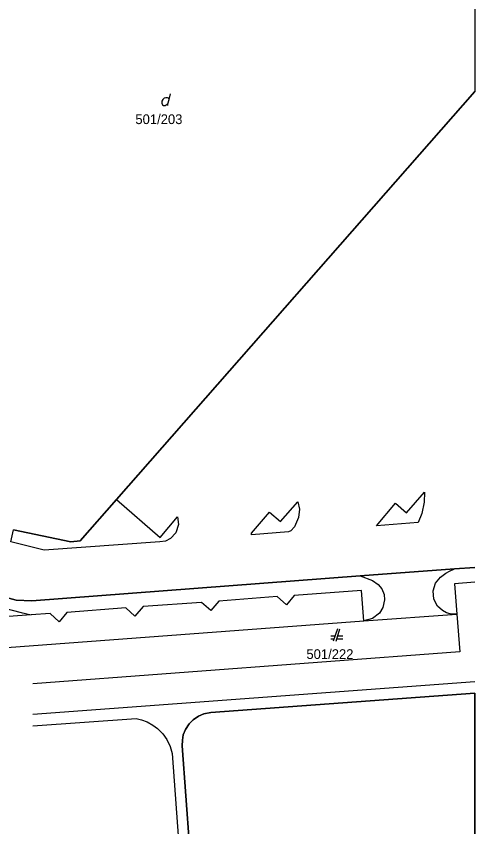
# Model space of a CAD drawing. Extents: x -264309 to -263505, y -1242443 to -1241763.
# Drawn here: x -263664.7 to -263589.3, y -1242279.4 to -1242146.2 of the extents above; entities that cross this region are included whole.
import ezdxf

# ---------------------------------------------------------------- set-up
doc = ezdxf.new("R2010")
doc.units = 0
for name, color, linetype in [('KN_2019_08_16', 7, 'Continuous'), ('KN_2019_08_16_KLADPAR', 7, 'Continuous'), ('KN_2019_08_16_ZAPPAR', 7, 'Continuous')]:
    doc.layers.add(name, color=color, linetype=linetype)

msp = doc.modelspace()

# ---------------------------------------------------------------- linework, layer by layer
at = {"layer": 'KN_2019_08_16'}
for p, q in [((-263689.32, -1242251.71), (-263607.55, -1242245.57)), ((-263607.55, -1242245.57), (-263592.26, -1242244.49)), ((-263592.26, -1242244.49), (-263591.75, -1242250.71)), ((-263591.75, -1242250.71), (-263661.97, -1242255.96))]:
    msp.add_line(p, q, dxfattribs=at)
at = {"layer": 'KN_2019_08_16_KLADPAR'}
for p, q in [((-263589.31, -1242136.09), (-263589.31, -1242158.57)), ((-263589.31, -1242158.57), (-263648.25, -1242225.66)), ((-263639.59, -1242159.89), (-263639.32, -1242158.99)), ((-263648.25, -1242225.66), (-263654.22, -1242232.42)), ((-263655.72, -1242232.61), (-263665.17, -1242230.64)), ((-263654.22, -1242232.42), (-263655.72, -1242232.61)), ((-263608.15, -1242238.19), (-263592.66, -1242237.06)), ((-263592.66, -1242237.06), (-263589.31, -1242236.82)), ((-263662.17, -1242242.32), (-263608.15, -1242238.19)), ((-263667.15, -1242241.55), (-263664.7, -1242242.17)), ((-263664.7, -1242242.17), (-263662.17, -1242242.32)), ((-263611.91, -1242246.93), (-263612.61, -1242248.93)), ((-263612.11, -1242248.93), (-263611.51, -1242246.93)), ((-263612.33, -1242248.13), (-263613.01, -1242248.13)), ((-263611.01, -1242248.13), (-263611.87, -1242248.13)), ((-263613.01, -1242248.53), (-263612.47, -1242248.53)), ((-263611.99, -1242248.53), (-263611.01, -1242248.53)), ((-263589.31, -1242257.5), (-263632.7, -1242260.67)), ((-263632.7, -1242260.67), (-263589.31, -1242257.5)), ((-263589.31, -1242316.35), (-263589.31, -1242257.5)), ((-263589.31, -1242257.5), (-263589.31, -1242316.35)), ((-263634.73, -1242261.26), (-263635.63, -1242261.87)), ((-263635.63, -1242261.87), (-263634.73, -1242261.26)), ((-263633.86, -1242260.9), (-263634.73, -1242261.26)), ((-263634.73, -1242261.26), (-263633.86, -1242260.9)), ((-263632.7, -1242260.67), (-263633.86, -1242260.9)), ((-263633.86, -1242260.9), (-263632.7, -1242260.67)), ((-263636.29, -1242262.54), (-263636.89, -1242263.47)), ((-263636.89, -1242263.47), (-263636.29, -1242262.54)), ((-263635.63, -1242261.87), (-263636.29, -1242262.54)), ((-263636.29, -1242262.54), (-263635.63, -1242261.87)), ((-263637.24, -1242264.33), (-263637.4, -1242265.2)), ((-263637.4, -1242265.2), (-263637.24, -1242264.33)), ((-263636.89, -1242263.47), (-263637.24, -1242264.33)), ((-263637.24, -1242264.33), (-263636.89, -1242263.47)), ((-263637.4, -1242265.2), (-263637.43, -1242266.15)), ((-263637.43, -1242266.15), (-263637.4, -1242265.2)), ((-263637.43, -1242266.15), (-263633.91, -1242314.48)), ((-263633.91, -1242314.48), (-263637.43, -1242266.15))]:
    msp.add_line(p, q, dxfattribs=at)
for points in [[(-263665.17, -1242230.64), (-263655.72, -1242232.61), (-263654.22, -1242232.42), (-263648.25, -1242225.66), (-263589.31, -1242158.57)], [(-263639.77, -1242160.88), (-263639.77, -1242160.61), (-263639.59, -1242159.89), (-263639.68, -1242159.71), (-263639.86, -1242159.62), (-263640.13, -1242159.62), (-263640.4, -1242159.71), (-263640.58, -1242159.89), (-263640.76, -1242160.16), (-263640.76, -1242160.52), (-263640.67, -1242160.79), (-263640.49, -1242160.88), (-263640.22, -1242160.88), (-263640.04, -1242160.79), (-263639.77, -1242160.61)], [(-263589.31, -1242236.82), (-263592.66, -1242237.06), (-263608.15, -1242238.19), (-263662.17, -1242242.32), (-263664.7, -1242242.17), (-263667.15, -1242241.55)]]:
    msp.add_lwpolyline(points, dxfattribs=at)
at = {"layer": 'KN_2019_08_16_ZAPPAR'}
for p, q in [((-263598.6, -1242229.45), (-263605.47, -1242229.95)), ((-263619.95, -1242230.99), (-263626.01, -1242231.45)), ((-263641.11, -1242232.58), (-263660.13, -1242233.99)), ((-263589.31, -1242239.25), (-263592.67, -1242239.5)), ((-263634.24, -1242242.56), (-263643.86, -1242243.26)), ((-263661.97, -1242260.91), (-263589.31, -1242255.57))]:
    msp.add_line(p, q, dxfattribs=at)
for points in [[(-263605.47, -1242229.95), (-263602.36, -1242226.23), (-263600.57, -1242227.85), (-263597.61, -1242224.45), (-263597.66, -1242226.07), (-263598, -1242227.95), (-263598.6, -1242229.45)], [(-263648.25, -1242225.66), (-263641.07, -1242231.91), (-263638.19, -1242228.5), (-263638.05, -1242229.78), (-263638.47, -1242231.1), (-263639.33, -1242232.07), (-263640.17, -1242232.49), (-263641.11, -1242232.58)], [(-263626.01, -1242231.45), (-263626.04, -1242231.19), (-263623.09, -1242227.72), (-263621.25, -1242229.25), (-263618.41, -1242226.02)], [(-263618.41, -1242226.02), (-263618.16, -1242227.26), (-263618.29, -1242228.59), (-263618.98, -1242230.12), (-263619.57, -1242230.81), (-263619.95, -1242230.99)], [(-263660.13, -1242233.99), (-263665.58, -1242232.61), (-263665.17, -1242230.64)], [(-263592.67, -1242239.5), (-263592.26, -1242244.49), (-263592.78, -1242244.51), (-263593.34, -1242244.45), (-263593.95, -1242244.28), (-263594.63, -1242243.87), (-263595.43, -1242243.19), (-263596.04, -1242242.01), (-263596.17, -1242240.67), (-263595.8, -1242239.42), (-263594.96, -1242238.39), (-263594.1, -1242237.75), (-263593.48, -1242237.41), (-263592.66, -1242237.06)], [(-263608.15, -1242238.19), (-263606.14, -1242238.95), (-263605.19, -1242239.61), (-263604.6, -1242240.34), (-263604.23, -1242241.28), (-263604.16, -1242242.12), (-263604.41, -1242243.4), (-263604.99, -1242244.34), (-263606.12, -1242245.2), (-263607.55, -1242245.57), (-263607.95, -1242240.58), (-263619.01, -1242241.42), (-263620.3, -1242242.96), (-263621.79, -1242241.61), (-263631.42, -1242242.36), (-263632.74, -1242243.87), (-263634.24, -1242242.56)], [(-263673.22, -1242240.46), (-263669.9, -1242242.67), (-263663.88, -1242244.2), (-263662.27, -1242244.61), (-263670.46, -1242245.18), (-263670.39, -1242250.29), (-263671.38, -1242250.29), (-263671.47, -1242245.27)], [(-263643.86, -1242243.26), (-263645.2, -1242244.8), (-263646.67, -1242243.44), (-263656.4, -1242244.2), (-263657.66, -1242245.73), (-263659.14, -1242244.4), (-263662.27, -1242244.61)], [(-263661.97, -1242262.84), (-263645, -1242261.62), (-263644.09, -1242261.84), (-263643.16, -1242262.2), (-263642.26, -1242262.71), (-263641.47, -1242263.31), (-263640.63, -1242264.16), (-263639.96, -1242265.08), (-263639.39, -1242266.26), (-263639.05, -1242267.4), (-263635.61, -1242314.61)]]:
    msp.add_lwpolyline(points, dxfattribs=at)

# ---------------------------------------------------------------- texts
at = {"layer": 'KN_2019_08_16_KLADPAR'}
for s, p in [('501/203', (-263645.12, -1242163.95)), ('501/222', (-263617, -1242251.86))]:
    msp.add_text(s, height=1.6, dxfattribs=at).set_placement(p)

doc.saveas('drawing.dxf')
